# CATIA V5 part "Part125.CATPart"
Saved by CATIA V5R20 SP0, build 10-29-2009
Part number: FA 084700-1
Revision: ANY
Definition: UNKNOWN
Nomenclature: FA 084700-1
Source: Unknown
Bounding box of the stored display mesh (mm): x -2.853 to 2.853, y 0.2 to 2.5, z -3 to 3
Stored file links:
  C:\Users\Utente\Desktop\IO LAVORO\3D X SITO CF\CUMSA\3D files FA\FA 084705-20\Part125.CATPart

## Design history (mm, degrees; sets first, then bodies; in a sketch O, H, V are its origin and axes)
Body1 "Cortar-Extruir1" (main body)
  Solid1: solid without history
